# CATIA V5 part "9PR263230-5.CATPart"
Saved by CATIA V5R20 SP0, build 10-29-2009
Part number: 9PR263230-5
Revision: ANY
Definition: UNKNOWN
Nomenclature: 9PR263230-5
Source: Unknown
Bounding box of the stored display mesh (mm): x -5 to 5, y -5 to 5, z -5 to 5
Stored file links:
  C:\Users\Utente\Desktop\IO LAVORO\3D X SITO CF\CUMSA\3D files PR.233230\PR 263230\9PR263230-5.CATPart
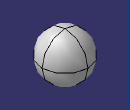
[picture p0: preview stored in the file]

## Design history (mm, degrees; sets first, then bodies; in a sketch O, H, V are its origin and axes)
Body1 "Revolución1" (main body)
  Solid1: solid without history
